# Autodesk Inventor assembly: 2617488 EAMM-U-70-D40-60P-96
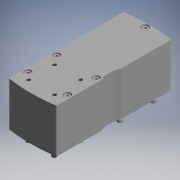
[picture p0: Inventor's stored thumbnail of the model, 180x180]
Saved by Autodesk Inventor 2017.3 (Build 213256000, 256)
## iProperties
Category: PARTsolutions
Company: FESTO
Part Number: 2617488 EAMM-U-70-D40-60P-96
Catalog Web Link: www.cadenas.de
Description: EAMM-U-parallel kit
Vendor: FESTO
Document SubType Name: Assembly
Designer: partserver
Manufacturer: FESTO
Mass: 1730 g
Surface Area: 1149.62 cm^2
Volume: 401.327 cm^3
Density: 4.3107 g/cm^3
Title: 2617488 EAMM-U-70-D40-60P-96
Author: Cadenas PARTsolutions
Comments: parallel kit
PSOL_IDENT_0: {ATYP=ASSISTANT},{DATA=script=$CADENAS_DATA/23d-libs/festo/webfesto.vbb&M_FAMILY=EAMM&M_GROUP=01&M_P
PSOL_IDENT_1: ARTNO=2617488&IDCODE1=EAMM-U-70-D40-60P-96&IDCODE2=&customer_number_cns=&MATES=1&LOD=HI&LOCKERP=0&SI
PSOL_IDENT_2: NGLEPART=1}
NB: 2617488 EAMM-U-70-D40-60P-96
NN: EAMM-U
NT: parallel kit
NBSYN: $TNR. $TYP.
LINA: 2617488 EAMM-U-70-D40-60P-96
CATALOG: Festo
TNR: 2617488
TYP: EAMM-U-70-D40-60P-96
B1: 70
B2: 0
B3: 38
B4: 0
B5: 38
B6: 58
D1: 50.5
D2: 70
D3: 40
D4: 5.300
D5: 6.6
D6: M6
D7: 0
H1: 173.5
H2: 0
H3: 38
H4: 0
H5: 38
H6: 34.5
H7: 96
H8: 10
H9: 32.5
H10: 100.5
H11: 0
H12: 2
L1: 64.5
L2: 0
L3: 0
L4: 0
T1: 15
W1: 45
W2: 0
CNSMASSEXACT: 1.73
SUPPLIER: FESTO
ARTICLENO: 2617488 EAMM-U-70-D40-60P-96
BOMINFO: 2617488 EAMM-U-70-D40-60P-96
CREATOR: CADENAS GmbH
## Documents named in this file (7)
- e:\temp\worker_11\temp\exporttempdir_6360_28_xBRU0\format_0\2617488 EAMM-U-70-D40-60P-96.iam
- e:\temp\worker_11\temp\exporttempdir_6360_28_xBRU0\format_0\2607475 EAMM-U-70-D40-60P-96---(UT).ipt
- e:\temp\worker_11\temp\exporttempdir_6360_28_xBRU0\format_0\2610112 EAMM-U-70-D40-___-173---(OT).ipt
- e:\temp\worker_11\temp\exporttempdir_6360_28_xBRU0\format_0\DIN-912 - M5x35(F).ipt
- e:\temp\worker_11\temp\exporttempdir_6360_28_xBRU0\format_0\DIN 557 - M4.ipt
- e:\temp\worker_11\temp\exporttempdir_6360_28_xBRU0\format_0\DIN-6912 - M6x18(F).ipt
- e:\temp\worker_11\temp\exporttempdir_6360_28_xBRU0\format_0\DIN-912 - M4x16(F).ipt
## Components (19 placed, 6 different names)
1. 2607475 EAMM-U-70-D40-60P-96---(UT):1 — AS_1_XY@1 <-> MONTAGE_XY@12, AS_1_Z@1 <-> MONTAGE_Z@12, AS_1_YZ@1 <-> MONTAGE_YZ@12, AS_2_XY@1 <-> MONTAGE_XY@13, AS_2_Z@1 <-> MONTAGE_Z@13, AS_2_YZ@1 <-> MONTAGE_YZ@13, AS_3_XY@1 <-> MONTAGE_XY@14, AS_3_Z@1 <-> MONTAGE_Z@14, AS_3_YZ@1 <-> MONTAGE_YZ@14, AS_4_XY@1 <-> MONTAGE_XY@15, AS_4_Z@1 <-> MONTAGE_Z@15, AS_4_YZ@1 <-> MONTAGE_YZ@15, MS_1_XY@1 <-> ANBAU_XY@16, MS_1_Z@1 <-> ANBAU_Z@16, MS_1_YZ@1 <-> ANBAU_YZ@16, MS_2_XY@1 <-> ANBAU_XY@17, MS_2_Z@1 <-> ANBAU_Z@17, MS_2_YZ@1 <-> ANBAU_YZ@17, MS_3_XY@1 <-> ANBAU_XY@18, MS_3_Z@1 <-> ANBAU_Z@18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
2. 2610112 EAMM-U-70-D40-___-173---(OT):1
3. DIN-912 - M5x35(F):1
4. DIN-912 - M5x35(F):2
5. DIN-912 - M5x35(F):3
6. DIN-912 - M5x35(F):4
7. DIN-912 - M5x35(F):5
8. DIN 557 - M4:1
9. DIN 557 - M4:2
10. DIN 557 - M4:3
11. DIN 557 - M4:4
12. DIN-6912 - M6x18(F):1 — AS_1_XY@1 <-> MONTAGE_XY@12, AS_1_Z@1 <-> MONTAGE_Z@12, AS_1_YZ@1 <-> MONTAGE_YZ@12
13. DIN-6912 - M6x18(F):2 — AS_2_XY@1 <-> MONTAGE_XY@13, AS_2_Z@1 <-> MONTAGE_Z@13, AS_2_YZ@1 <-> MONTAGE_YZ@13
14. DIN-6912 - M6x18(F):3 — AS_3_XY@1 <-> MONTAGE_XY@14, AS_3_Z@1 <-> MONTAGE_Z@14, AS_3_YZ@1 <-> MONTAGE_YZ@14
15. DIN-6912 - M6x18(F):4 — AS_4_XY@1 <-> MONTAGE_XY@15, AS_4_Z@1 <-> MONTAGE_Z@15, AS_4_YZ@1 <-> MONTAGE_YZ@15
16. DIN-912 - M4x16(F):1 — MS_1_XY@1 <-> ANBAU_XY@16, MS_1_Z@1 <-> ANBAU_Z@16, MS_1_YZ@1 <-> ANBAU_YZ@16
17. DIN-912 - M4x16(F):2 — MS_2_XY@1 <-> ANBAU_XY@17, MS_2_Z@1 <-> ANBAU_Z@17, MS_2_YZ@1 <-> ANBAU_YZ@17
18. DIN-912 - M4x16(F):3 — MS_3_XY@1 <-> ANBAU_XY@18, MS_3_Z@1 <-> ANBAU_Z@18, MS_3_YZ@1 <-> ANBAU_YZ@18
19. DIN-912 - M4x16(F):4 — MS_4_XY@1 <-> ANBAU_XY@19, MS_4_Z@1 <-> ANBAU_Z@19, MS_4_YZ@1 <-> ANBAU_YZ@19
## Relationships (24: Mate 16, Angle 8)
- AS_1_XY@1 <-> MONTAGE_XY@12 [Mate]: 2607475 EAMM-U-70-D40-60P-96---(UT):1 ↔ DIN-6912 - M6x18(F):1
- AS_1_Z@1 <-> MONTAGE_Z@12 [Mate]: 2607475 EAMM-U-70-D40-60P-96---(UT):1 ↔ DIN-6912 - M6x18(F):1
- AS_1_YZ@1 <-> MONTAGE_YZ@12 [Angle]: 2607475 EAMM-U-70-D40-60P-96---(UT):1 ↔ DIN-6912 - M6x18(F):1
- AS_2_XY@1 <-> MONTAGE_XY@13 [Mate]: 2607475 EAMM-U-70-D40-60P-96---(UT):1 ↔ DIN-6912 - M6x18(F):2
- AS_2_Z@1 <-> MONTAGE_Z@13 [Mate]: 2607475 EAMM-U-70-D40-60P-96---(UT):1 ↔ DIN-6912 - M6x18(F):2
- AS_2_YZ@1 <-> MONTAGE_YZ@13 [Angle]: 2607475 EAMM-U-70-D40-60P-96---(UT):1 ↔ DIN-6912 - M6x18(F):2
- AS_3_XY@1 <-> MONTAGE_XY@14 [Mate]: 2607475 EAMM-U-70-D40-60P-96---(UT):1 ↔ DIN-6912 - M6x18(F):3
- AS_3_Z@1 <-> MONTAGE_Z@14 [Mate]: 2607475 EAMM-U-70-D40-60P-96---(UT):1 ↔ DIN-6912 - M6x18(F):3
- AS_3_YZ@1 <-> MONTAGE_YZ@14 [Angle]: 2607475 EAMM-U-70-D40-60P-96---(UT):1 ↔ DIN-6912 - M6x18(F):3
- AS_4_XY@1 <-> MONTAGE_XY@15 [Mate]: 2607475 EAMM-U-70-D40-60P-96---(UT):1 ↔ DIN-6912 - M6x18(F):4
- AS_4_Z@1 <-> MONTAGE_Z@15 [Mate]: 2607475 EAMM-U-70-D40-60P-96---(UT):1 ↔ DIN-6912 - M6x18(F):4
- AS_4_YZ@1 <-> MONTAGE_YZ@15 [Angle]: 2607475 EAMM-U-70-D40-60P-96---(UT):1 ↔ DIN-6912 - M6x18(F):4
- MS_1_XY@1 <-> ANBAU_XY@16 [Mate]: 2607475 EAMM-U-70-D40-60P-96---(UT):1 ↔ DIN-912 - M4x16(F):1
- MS_1_Z@1 <-> ANBAU_Z@16 [Mate]: 2607475 EAMM-U-70-D40-60P-96---(UT):1 ↔ DIN-912 - M4x16(F):1
- MS_1_YZ@1 <-> ANBAU_YZ@16 [Angle]: 2607475 EAMM-U-70-D40-60P-96---(UT):1 ↔ DIN-912 - M4x16(F):1
- MS_2_XY@1 <-> ANBAU_XY@17 [Mate]: 2607475 EAMM-U-70-D40-60P-96---(UT):1 ↔ DIN-912 - M4x16(F):2
- MS_2_Z@1 <-> ANBAU_Z@17 [Mate]: 2607475 EAMM-U-70-D40-60P-96---(UT):1 ↔ DIN-912 - M4x16(F):2
- MS_2_YZ@1 <-> ANBAU_YZ@17 [Angle]: 2607475 EAMM-U-70-D40-60P-96---(UT):1 ↔ DIN-912 - M4x16(F):2
- MS_3_XY@1 <-> ANBAU_XY@18 [Mate]: 2607475 EAMM-U-70-D40-60P-96---(UT):1 ↔ DIN-912 - M4x16(F):3
- MS_3_Z@1 <-> ANBAU_Z@18 [Mate]: 2607475 EAMM-U-70-D40-60P-96---(UT):1 ↔ DIN-912 - M4x16(F):3
- MS_3_YZ@1 <-> ANBAU_YZ@18 [Angle]: 2607475 EAMM-U-70-D40-60P-96---(UT):1 ↔ DIN-912 - M4x16(F):3
- MS_4_XY@1 <-> ANBAU_XY@19 [Mate]: 2607475 EAMM-U-70-D40-60P-96---(UT):1 ↔ DIN-912 - M4x16(F):4
- MS_4_Z@1 <-> ANBAU_Z@19 [Mate]: 2607475 EAMM-U-70-D40-60P-96---(UT):1 ↔ DIN-912 - M4x16(F):4
- MS_4_YZ@1 <-> ANBAU_YZ@19 [Angle]: 2607475 EAMM-U-70-D40-60P-96---(UT):1 ↔ DIN-912 - M4x16(F):4
